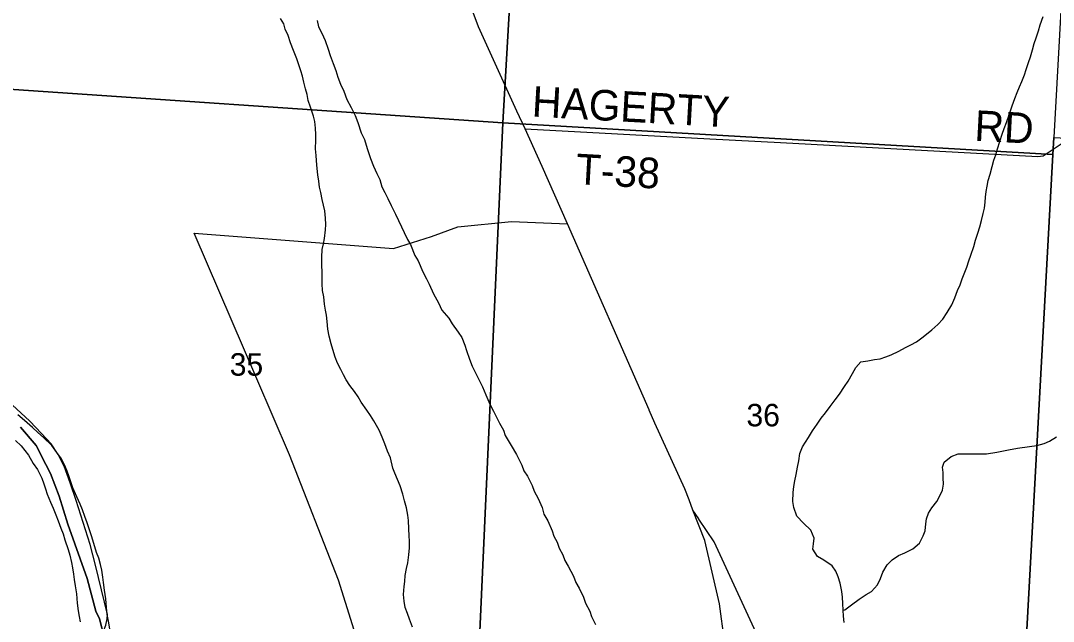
# Model space of a CAD drawing. Extents: x 1643459 to 2064572, y 425441 to 780708.
# Drawn here: x 1832459 to 1842600, y 603499 to 609399 of the extents above; entities that cross this region are included whole.
import ezdxf

# ---------------------------------------------------------------- set-up
doc = ezdxf.new("R2010")
doc.units = 0
for name, color, linetype in [('GM_X_Adjacent_County', 7, 'Continuous'), ('GM_X_City_Street', 7, 'Continuous'), ('GM_X_Major_River', 7, 'Continuous'), ('GM_X_Major_River_Text', 7, 'Continuous'), ('GM_X_Minor_Lake', 7, 'Continuous'), ('GM_X_State_Route', 7, 'Continuous'), ('GM_X_Unincorporated_Text', 7, 'Continuous'), ('GM_X_US_Route', 7, 'Continuous'), ('RD_X_Wall', 7, 'Continuous')]:
    doc.layers.add(name, color=color, linetype=linetype)

msp = doc.modelspace()

# ---------------------------------------------------------------- linework, layer by layer
at = {"layer": 'GM_X_City_Street'}
for points in [[(1832458, 605407), (1832613, 605226), (1832707, 605041), (1832753, 604952), (1832836, 604727), (1832921, 604454), (1833111, 603919), (1833196, 603598), (1833235, 603525), (1833283, 603334)], [(1851890, 602317), (1849051, 602434), (1847771, 602487), (1839937, 602900), (1839420, 602936), (1835806, 603183), (1833283, 603334), (1833235, 603525), (1833196, 603598), (1833111, 603919), (1832921, 604454), (1832836, 604727), (1832753, 604952), (1832707, 605041), (1832613, 605226), (1832458, 605407)]]:
    msp.add_lwpolyline(points, dxfattribs=at)
at = {"layer": 'GM_X_Major_River_Text'}
for points in [[(1837413, 608336), (1839226, 608239), (1839226, 608239)], [(1839226, 608239), (1839920, 608202), (1839920, 608202)], [(1839920, 608202), (1842448, 608066), (1842499, 608073), (1842687, 608195), (1842757, 608206), (1843884, 608148), (1849303, 607884)], [(1835803, 603192), (1835580, 603905), (1835098, 605134), (1834779, 605882), (1834163, 607311), (1836120, 607161), (1836492, 607280), (1836751, 607373), (1837278, 607428), (1837829, 607405)]]:
    msp.add_lwpolyline(points, dxfattribs=at)
at = {"layer": 'GM_X_Minor_Lake'}
for points in [[(1839118, 604505), (1839060, 604590)], [(1839937, 602900), (1839740, 603257), (1839269, 604281), (1839118, 604504), (1839118, 604505)]]:
    msp.add_lwpolyline(points, dxfattribs=at)
at = {"layer": 'GM_X_State_Route'}
for points in [[(1832124, 614096), (1837502, 613740), (1837195, 608395), (1831814, 608761)], [(1842889, 613414), (1842604, 608253), (1842595, 608085), (1837195, 608395), (1837502, 613740)], [(1842595, 608085), (1842304, 602757), (1841286, 602812), (1836955, 603110), (1837195, 608395)], [(1842595, 608085), (1842604, 608253), (1846583, 608042), (1846349, 602557), (1842304, 602757)]]:
    msp.add_lwpolyline(points, close=True, dxfattribs=at)
msp.add_lwpolyline([(1831814, 608761), (1837195, 608395), (1836955, 603110), (1836023, 603169), (1833250, 603342), (1833295, 603462), (1833309, 603524), (1833311, 603566), (1833194, 604051), (1833141, 604253), (1833003, 604686), (1832944, 604860), (1832888, 605022), (1832829, 605138), (1832759, 605243), (1832664, 605343), (1832548, 605466), (1832377, 605625)], dxfattribs=at)
at = {"layer": 'GM_X_Unincorporated_Text'}
for points in [[(1833335, 603426), (1833322, 603500), (1833310, 603566), (1833302, 603635), (1833295, 603719), (1833283, 603805), (1833273, 603880), (1833267, 603932), (1833256, 604002), (1833242, 604056), (1833226, 604119), (1833204, 604175), (1833157, 604328), (1833133, 604408), (1833113, 604468), (1833089, 604529), (1833066, 604593), (1833044, 604651), (1833012, 604722), (1832970, 604810), (1832937, 604919), (1832915, 604975), (1832889, 605035), (1832853, 605104), (1832813, 605158), (1832764, 605226), (1832684, 605305), (1832628, 605355), (1832576, 605404), (1832496, 605472), (1832432, 605527)], [(1832407, 605274), (1832463, 605222), (1832536, 605131), (1832582, 605050), (1832624, 604990), (1832666, 604904), (1832688, 604849), (1832703, 604799), (1832721, 604749), (1832753, 604668), (1832777, 604612), (1832805, 604546), (1832828, 604486), (1832854, 604413), (1832876, 604357), (1832894, 604301), (1832927, 604204), (1832941, 604150), (1832957, 604076), (1832967, 604023), (1832977, 603963), (1832986, 603911), (1832996, 603847), (1833006, 603768), (1833015, 603676), (1833025, 603602), (1833035, 603545), (1833045, 603493)]]:
    msp.add_lwpolyline(points, dxfattribs=at)
at = {"layer": 'GM_X_US_Route'}
for points in [[(1836062, 605170), (1836036, 605242), (1836010, 605309), (1835981, 605377), (1835927, 605470), (1835895, 605520), (1835859, 605574), (1835803, 605653), (1835773, 605703), (1835736, 605757), (1835692, 605814), (1835656, 605870), (1835630, 605920), (1835602, 605973), (1835570, 606035), (1835548, 606095), (1835525, 606170), (1835509, 606224), (1835489, 606300), (1835475, 606369), (1835470, 606443), (1835462, 606505), (1835454, 606555), (1835444, 606614), (1835435, 606686), (1835423, 606750), (1835419, 606814), (1835420, 606935), (1835418, 606991), (1835418, 607077), (1835421, 607152), (1835433, 607206), (1835443, 607258), (1835454, 607344), (1835456, 607398), (1835454, 607460), (1835445, 607531), (1835421, 607643), (1835407, 607710), (1835395, 607764), (1835386, 607822), (1835378, 607886), (1835366, 607979), (1835361, 608075), (1835355, 608139), (1835357, 608226), (1835358, 608280), (1835356, 608344), (1835348, 608408), (1835334, 608460), (1835305, 608549), (1835283, 608615), (1835271, 608675), (1835257, 608730), (1835240, 608796), (1835226, 608854), (1835210, 608907), (1835192, 608965), (1835172, 609023), (1835137, 609106), (1835109, 609180), (1835087, 609252), (1835057, 609315), (1835043, 609367), (1835012, 609419)], [(1835371, 609402), (1835384, 609339), (1835418, 609277), (1835448, 609203), (1835478, 609120), (1835500, 609058), (1835527, 608979), (1835553, 608909), (1835575, 608843), (1835601, 608776), (1835632, 608706), (1835662, 608624), (1835706, 608545), (1835744, 608467), (1835771, 608400), (1835803, 608296), (1835835, 608232), (1835861, 608145), (1835896, 608045), (1835924, 607970), (1835956, 607898), (1835986, 607840), (1836007, 607767), (1836035, 607711), (1836065, 607653), (1836099, 607582), (1836139, 607498), (1836200, 607373), (1836226, 607319), (1836258, 607250), (1836288, 607200), (1836331, 607091), (1836363, 607041), (1836407, 606933), (1836445, 606864), (1836469, 606812), (1836514, 606717), (1836562, 606627), (1836596, 606554), (1836664, 606478), (1836696, 606420), (1836755, 606339), (1836791, 606287), (1836821, 606212), (1836837, 606160), (1836867, 606074), (1836894, 606007), (1836928, 605935), (1836994, 605802), (1837028, 605724), (1837067, 605633), (1837103, 605563), (1837135, 605498), (1837161, 605444), (1837201, 605376), (1837218, 605326), (1837276, 605227), (1837328, 605138), (1837382, 605032), (1837401, 604978), (1837435, 604925), (1837483, 604833), (1837501, 604776), (1837541, 604706), (1837580, 604616), (1837598, 604553), (1837636, 604485), (1837678, 604388), (1837696, 604336), (1837729, 604276), (1837747, 604219), (1837783, 604153), (1837803, 604095), (1837837, 604042), (1837888, 603944), (1837910, 603880), (1837942, 603825), (1837986, 603737), (1838006, 603678), (1838049, 603600), (1838065, 603546), (1838105, 603469)], [(1840457, 605675), (1840499, 605729), (1840549, 605805), (1840584, 605857), (1840626, 605935), (1840661, 605991), (1840709, 606049), (1840777, 606059), (1840844, 606071), (1840898, 606078), (1840954, 606096), (1841008, 606118), (1841081, 606154), (1841149, 606190), (1841201, 606215), (1841256, 606243), (1841322, 606293), (1841405, 606361), (1841465, 606415), (1841514, 606467), (1841558, 606531), (1841603, 606609), (1841631, 606677), (1841659, 606749), (1841684, 606805), (1841704, 606862), (1841749, 606978), (1841771, 607040), (1841789, 607096), (1841818, 607182), (1841836, 607242), (1841859, 607312), (1841877, 607375), (1841895, 607435), (1841912, 607505), (1841924, 607557), (1841930, 607615), (1841934, 607667), (1841941, 607720), (1841951, 607774), (1841961, 607830), (1841978, 607890), (1841998, 607966), (1842016, 608030), (1842035, 608080), (1842053, 608139), (1842075, 608213), (1842098, 608283), (1842116, 608339), (1842140, 608399), (1842167, 608473), (1842195, 608561), (1842222, 608634), (1842246, 608692), (1842268, 608750), (1842289, 608802), (1842317, 608868), (1842333, 608918), (1842356, 608988), (1842374, 609044), (1842396, 609114), (1842413, 609175), (1842431, 609229), (1842453, 609299), (1842472, 609357), (1842500, 609439)], [(1840547, 603487), (1840539, 603549), (1840536, 603609), (1840534, 603674), (1840530, 603738), (1840524, 603792), (1840507, 603874), (1840487, 603937), (1840465, 603991), (1840429, 604043), (1840345, 604100), (1840283, 604136), (1840237, 604209), (1840246, 604261), (1840250, 604315), (1840218, 604395), (1840148, 604464), (1840080, 604531), (1840051, 604617), (1840041, 604677), (1840045, 604763), (1840051, 604824), (1840060, 604880), (1840074, 604942), (1840088, 605012), (1840099, 605074), (1840109, 605149), (1840137, 605213), (1840196, 605305), (1840235, 605369), (1840279, 605437), (1840321, 605495), (1840362, 605547), (1840408, 605609), (1840457, 605675)], [(1840536, 603609), (1840552, 603613), (1840618, 603661), (1840693, 603717), (1840761, 603761), (1840813, 603791), (1840872, 603859), (1840902, 603921), (1840927, 603983), (1840967, 604053), (1841017, 604103), (1841080, 604145), (1841142, 604171), (1841221, 604210), (1841287, 604266), (1841321, 604339), (1841342, 604389), (1841348, 604457), (1841354, 604507), (1841373, 604563), (1841405, 604615), (1841455, 604677), (1841490, 604739), (1841512, 604789), (1841520, 604845), (1841519, 604908), (1841517, 604960), (1841511, 605014), (1841527, 605064), (1841596, 605118), (1841664, 605144), (1841734, 605144), (1841809, 605145), (1841943, 605145), (1842044, 605160), (1842160, 605184), (1842248, 605201), (1842365, 605217), (1842437, 605227), (1842509, 605247), (1842562, 605268), (1842630, 605312)], [(1836307, 603443), (1836279, 603521), (1836257, 603576), (1836236, 603634), (1836224, 603696), (1836218, 603762), (1836225, 603841), (1836231, 603891), (1836235, 603949), (1836247, 604017), (1836260, 604075), (1836272, 604152), (1836276, 604222), (1836279, 604288), (1836275, 604340), (1836271, 604408), (1836268, 604491), (1836260, 604541), (1836248, 604613), (1836230, 604682), (1836213, 604748), (1836185, 604830), (1836161, 604893), (1836135, 604955), (1836113, 605005), (1836090, 605104), (1836062, 605170)]]:
    msp.add_lwpolyline(points, dxfattribs=at)
at = {"layer": 'RD_X_Wall'}
for points in [[(1838632, 605574), (1838631, 605575), (1837829, 607405), (1837580, 607966), (1837413, 608336), (1837332, 608510), (1836956, 609337), (1836784, 609797), (1836776, 609816)], [(1841570, 590051), (1841464, 590384), (1840952, 591925), (1840750, 592618), (1840551, 593207), (1840454, 593588), (1840392, 593881), (1840336, 594171), (1840299, 594426), (1840171, 595596), (1840015, 596921), (1839914, 597835), (1839752, 599409), (1839627, 600488), (1839512, 601581), (1839420, 602936), (1839323, 603672), (1839178, 604294), (1839060, 604590), (1839024, 604692), (1838981, 604799), (1838688, 605446), (1838632, 605574)]]:
    msp.add_lwpolyline(points, dxfattribs=at)

# ---------------------------------------------------------------- texts
at = {"layer": 'GM_X_Adjacent_County'}
for s, p in [('35', (1834512, 605912)), ('36', (1839586, 605414))]:
    msp.add_text(s, height=221, rotation=0, dxfattribs=at).set_placement(p)
at = {"layer": 'GM_X_Major_River'}
for s, rotation, p in [('HAGERTY', 356.8362, (1837474, 608458)), ('RD', 357.0387, (1841820, 608220)), ('T-38', 356.8205, (1837905, 607794))]:
    msp.add_text(s, height=300, rotation=rotation, dxfattribs=at).set_placement(p)

doc.saveas('drawing.dxf')
